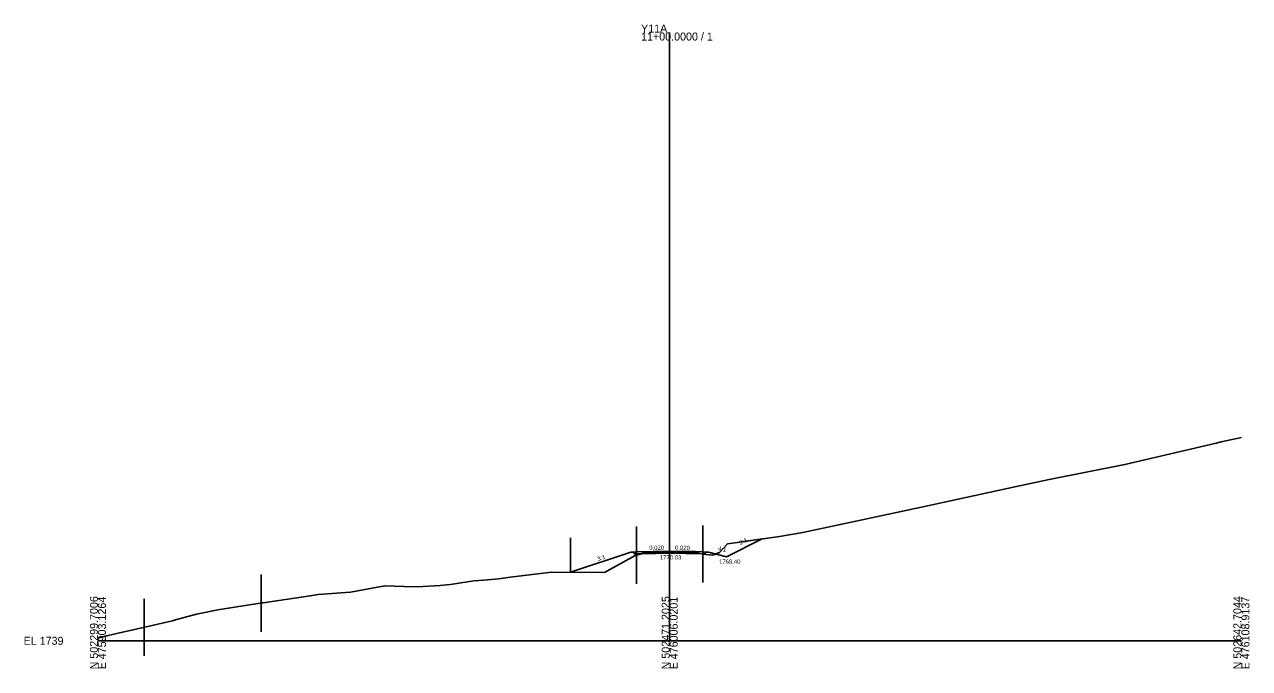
# Model space of a CAD drawing. Extents: x -26 to 403, y -10 to 5098.
# Drawn here: x -25.7 to 402.8, y 990.3 to 1215.5 of the extents above; entities that cross this region are included whole.
import ezdxf

# ---------------------------------------------------------------- set-up
doc = ezdxf.new("R2010")
doc.units = 0
for name, color, linetype in [('Exist Cross Section Cell', 7, 'Continuous'), ('Exist XS Center Line Elevation Label', 7, 'Continuous'), ('Exist XS Ground Line', 7, 'Continuous'), ('Prop XS Ditch Slope Text', 7, 'Continuous'), ('Prop XS Ditch Standard Text', 7, 'Continuous'), ('Prop XS Dump Level', 7, 'Continuous'), ('Prop XS Earthwork Shape', 7, 'Continuous'), ('Prop XS EOT Tick Mark', 7, 'Continuous'), ('Prop XS Finish Grade', 7, 'Continuous'), ('Prop XS Finish Grade Earthwork', 7, 'Continuous'), ('Prop XS Finish Grade Pavement', 7, 'Continuous'), ('Prop XS Pvmt Edge Slope', 7, 'Continuous'), ('Prop XS SE Text', 7, 'Continuous'), ('Prop XS Shoulder Borrow Shape', 7, 'Continuous'), ('Prop XS Side Slope Text', 7, 'Continuous'), ('Prop XS Subgrade Earthwork', 7, 'Continuous'), ('Scratch_Level_5', 7, 'Continuous')]:
    doc.layers.add(name, color=color, linetype=linetype)

msp = doc.modelspace()

# ---------------------------------------------------------------- linework, layer by layer
at = {"layer": 'Exist Cross Section Cell'}
for p, q in [((200, 1000), (200, 1212.74)), ((0, 1000), (200, 1000)), ((200, 1000), (400, 1000))]:
    msp.add_line(p, q, dxfattribs=at)
at = {"layer": 'Exist XS Ground Line'}
msp.add_lwpolyline([(0, 1000.97), (3.11, 1001.74), (7.12, 1002.67), (13.81, 1004.18), (25.05, 1006.76), (26.08, 1007.02), (27.16, 1007.27), (34.5, 1009.34), (41.91, 1010.82), (57.47, 1013.24), (57.77, 1013.29), (74.24, 1015.7), (77.04, 1016.18), (88.32, 1016.97), (100.32, 1019.22), (107.16, 1018.94), (111.65, 1018.89), (119.76, 1019.39), (121.98, 1019.61), (123.31, 1019.67), (131.46, 1021), (134.97, 1021.2), (140.09, 1021.61), (144.2, 1022.29), (157.76, 1023.93), (158.54, 1023.99), (177.17, 1023.87), (187.92, 1029.79), (190.6, 1030.61), (191.26, 1030.64), (198.56, 1031.06), (200, 1031.03), (209.42, 1030.78), (212.7, 1030.17), (215.01, 1029.91), (217.06, 1030.71), (217.39, 1030.9), (220.22, 1033.85), (223.62, 1034.36), (238.37, 1036.48), (246.6, 1037.93), (284.26, 1045.88), (285.75, 1046.21), (286.47, 1046.38), (320.69, 1053.83), (332.71, 1056.36), (359.27, 1061.65), (391.22, 1069.16), (392.87, 1069.53), (400, 1071.08)], dxfattribs=at)
at = {"layer": 'Prop XS Dump Level'}
for p, q in [((200, 1031.37), (188.4, 1031.13)), ((209, 1031.19), (200, 1031.37))]:
    msp.add_line(p, q, dxfattribs=at)
at = {"layer": 'Prop XS Earthwork Shape'}
for points in [[(216.12, 1030.34), (217.06, 1030.71), (217.39, 1030.9), (220.22, 1033.85), (223.62, 1034.36), (232.31, 1035.61), (219.89, 1029.4)], [(165.32, 1023.95), (177.17, 1023.87), (187.92, 1029.79), (190.11, 1030.46), (188.4, 1030.42), (187.68, 1030.41), (187.07, 1031.03), (186.4, 1030.97)], [(200, 1030.66), (190.11, 1030.46), (190.6, 1030.61), (191.26, 1030.64), (198.56, 1031.06), (200, 1031.03), (209.42, 1030.78), (211.27, 1030.43)], [(211.6, 1030.42), (211.27, 1030.43), (212.7, 1030.17), (215.01, 1029.91), (216.12, 1030.34), (213.6, 1030.97), (212.93, 1031.03), (212.32, 1030.41)]]:
    msp.add_lwpolyline(points, close=True, dxfattribs=at)
at = {"layer": 'Prop XS EOT Tick Mark'}
for p, q in [((188.4, 1031.13), (188.4, 1032.13)), ((211.6, 1031.13), (211.6, 1032.13))]:
    msp.add_line(p, q, dxfattribs=at)
at = {"layer": 'Prop XS Finish Grade'}
for p, q in [((188.4, 1031.13), (187.07, 1031.03)), ((211.6, 1031.13), (212.93, 1031.03))]:
    msp.add_line(p, q, dxfattribs=at)
at = {"layer": 'Prop XS Finish Grade Earthwork'}
for p, q in [((219.89, 1029.4), (232.31, 1035.61)), ((186.4, 1030.97), (165.32, 1023.95)), ((187.07, 1031.03), (186.4, 1030.97)), ((212.93, 1031.03), (213.6, 1030.97)), ((213.6, 1030.97), (219.89, 1029.4))]:
    msp.add_line(p, q, dxfattribs=at)
at = {"layer": 'Prop XS Finish Grade Pavement'}
for p, q in [((188.4, 1031.13), (200, 1031.37)), ((200, 1031.37), (211.6, 1031.13))]:
    msp.add_line(p, q, dxfattribs=at)
at = {"layer": 'Prop XS Pvmt Edge Slope'}
for p, q in [((188.4, 1031.13), (187.68, 1030.41)), ((211.6, 1031.13), (212.32, 1030.41))]:
    msp.add_line(p, q, dxfattribs=at)
at = {"layer": 'Prop XS Shoulder Borrow Shape'}
for points in [[(188.4, 1031.13), (187.07, 1031.03), (187.68, 1030.41)], [(211.6, 1031.13), (212.93, 1031.03), (212.32, 1030.41)]]:
    msp.add_lwpolyline(points, close=True, dxfattribs=at)
at = {"layer": 'Prop XS Subgrade Earthwork'}
for p, q in [((187.68, 1030.41), (187.07, 1031.03)), ((188.4, 1030.42), (187.68, 1030.41)), ((200, 1030.66), (188.4, 1030.42)), ((211.6, 1030.42), (200, 1030.66)), ((211.6, 1030.42), (212.32, 1030.41)), ((212.32, 1030.41), (212.93, 1031.03))]:
    msp.add_line(p, q, dxfattribs=at)
at = {"layer": 'Scratch_Level_5'}
for p, q in [((188.4, 1039.93), (188.4, 1019.93)), ((211.6, 1040.37), (211.6, 1020.37)), ((165.32, 1023.95), (165.32, 1035.95)), ((57.05, 1023.17), (57.05, 1003.17)), ((16.18, 1014.72), (16.18, 994.72))]:
    msp.add_line(p, q, dxfattribs=at)

# ---------------------------------------------------------------- texts
at = {"layer": 'Exist Cross Section Cell'}
for s, p in [('Y11A', (190, 1212.74)), ('11+00.0000 / 1', (190, 1209.94)), ('EL 1739', (-26, 998.6))]:
    msp.add_text(s, height=2.8, dxfattribs=at).set_placement(p)
for s, p in [('N 502299.7006', (0, 990)), ('E 475903.1264', (2.8, 990)), ('N 502471.2025', (200, 990)), ('E 476006.0201', (202.8, 990)), ('N 502642.7044', (400, 990)), ('E 476108.9137', (402.8, 990))]:
    msp.add_text(s, height=2.8, rotation=90, dxfattribs=at).set_placement(p)
at = {"layer": 'Exist XS Center Line Elevation Label'}
msp.add_text('1770.03', height=1.5, dxfattribs=at).set_placement((196.57, 1028.45))
at = {"layer": 'Prop XS Ditch Slope Text'}
msp.add_text('4:1', height=1.5, rotation=345.9638, dxfattribs=at).set_placement((216.81, 1031.72))
at = {"layer": 'Prop XS Ditch Standard Text'}
msp.add_text('1768.40', height=1.5, dxfattribs=at).set_placement((217.28, 1026.93))
at = {"layer": 'Prop XS Dump Level'}
for p in [(186.4, 1030.93), (213.6, 1030.93)]:
    msp.add_text('Case1', height=0.04, dxfattribs=at).set_placement(p)
at = {"layer": 'Prop XS SE Text'}
for rotation, p in [(1.1458, (192.88, 1031.72)), (358.8542, (201.88, 1031.83))]:
    msp.add_text('0.020', height=1.5, rotation=rotation, dxfattribs=at).set_placement(p)
at = {"layer": 'Prop XS Side Slope Text'}
for s, rotation, p in [('2:1', 26.5651, (224.8, 1033.47)), ('3:1', 18.4349, (174.93, 1027.84))]:
    msp.add_text(s, height=1.5, rotation=rotation, dxfattribs=at).set_placement(p)

doc.saveas('drawing.dxf')
